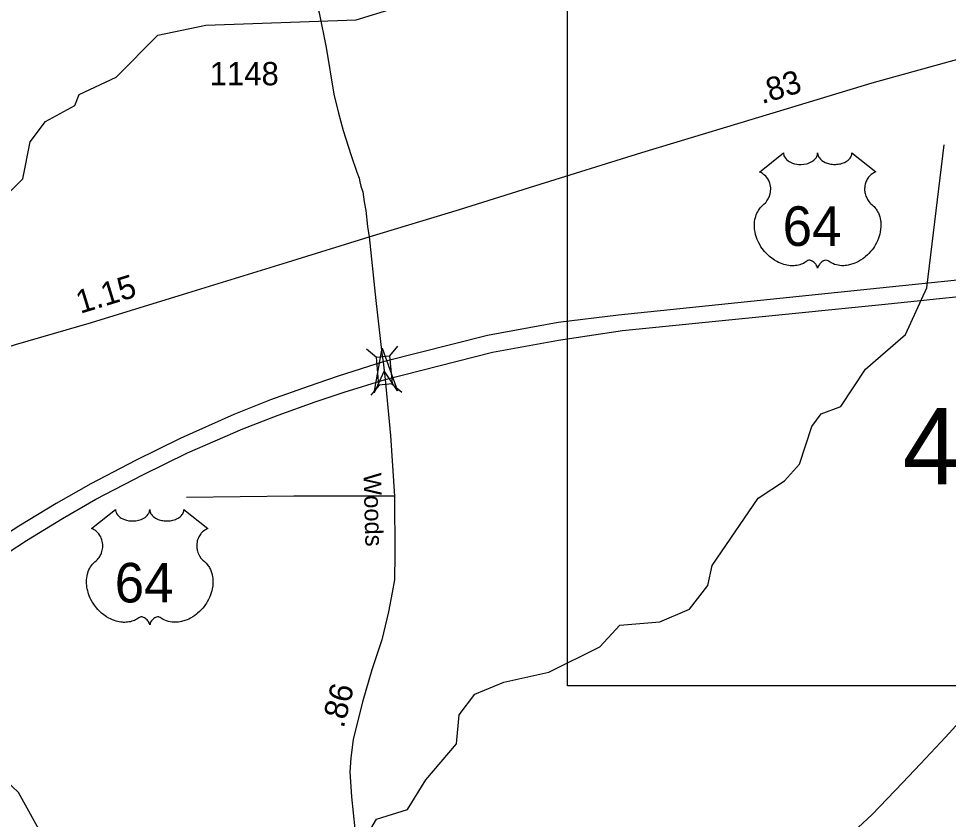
# Model space of a CAD drawing. Extents: x 2220236 to 2384410, y 720751 to 894131.
# Drawn here: x 2253834 to 2258834, y 792188 to 796491 of the extents above; entities that cross this region are included whole.
import ezdxf

# ---------------------------------------------------------------- set-up
doc = ezdxf.new("R2010")
doc.units = 0
for name, color, linetype in [('Exist Hydrographic Misc Water Feature', 7, 'Continuous'), ('Exist Hydrographic River Shore', 7, 'Continuous'), ('Exist Road Non-System Type 51', 7, 'Continuous'), ('Exist Road Primary US Attributed', 7, 'Continuous'), ('Exist Road Primary US Divided Attributed', 7, 'Continuous'), ('Exist Road Primary US Mileage Hundredths English Label', 7, 'Continuous'), ('Exist Road Primary US Shield CELL', 7, 'Continuous'), ('Exist Road Primary US Shield Number Label', 7, 'Continuous'), ('Exist Road Secondary Mileage Hundredths English Label', 7, 'Continuous'), ('Exist Road Secondary Structure Standard Bridge Attributed CELL', 7, 'Continuous'), ('Exist Road Secondary Structure Standard Bridge CELL', 7, 'Continuous'), ('Exist Road Secondary Structure Standard Bridge Number Label', 7, 'Continuous'), ('Exist Road Secondary Type 51 Attributed', 7, 'Continuous'), ('Exist Road Secondary Type 51 Label', 7, 'Continuous'), ('Exist Road Secondary Type 51 Number Label', 7, 'Continuous'), ('Map Preparation Inset Cut Line', 7, 'Continuous')]:
    doc.layers.add(name, color=color, linetype=linetype)

msp = doc.modelspace()

# ---------------------------------------------------------------- linework, layer by layer
at = {"layer": 'Exist Hydrographic Misc Water Feature'}
for points in [[(2253748.7, 795519.9), (2253856.7, 795629.2), (2253896.7, 795828.5), (2253978.8, 795938.3), (2254136.6, 796023.6), (2254160.8, 796082.2), (2254359.7, 796176.4), (2254583.7, 796401.4), (2254840.8, 796455.2), (2255648.7, 796484.4), (2255848.8, 796545.9), (2256338.7, 796607.9), (2256961.9, 796903.4), (2257160.8, 796938.6), (2257452.8, 796949.1), (2257775.7, 797103.1), (2258333.9, 797130.9), (2258574.8, 797201.4)], [(2255388.7, 791559.9), (2255758.8, 792188.6), (2255924.7, 792241), (2256023.7, 792399.6), (2256188.8, 792593), (2256203.8, 792750.2), (2256286.8, 792860), (2256443.7, 792925.6), (2256685.6, 792979.7), (2256958.8, 793115.1), (2257066.8, 793230.9), (2257282.8, 793249.4), (2257440.7, 793318.3), (2257539.7, 793444.2), (2257563.7, 793551.9), (2257810.8, 793914.2), (2257951.9, 794006.4), (2258033.7, 794096.6), (2258098.7, 794298.6), (2258148.7, 794366.5), (2258255.7, 794406.8), (2258387.8, 794607.5), (2258602.7, 794793.3), (2258717.7, 795043.5), (2258810.8, 795812.4)]]:
    msp.add_lwpolyline(points, dxfattribs=at)
at = {"layer": 'Exist Hydrographic River Shore'}
msp.add_lwpolyline([(2254150.4, 790183.6), (2254130.6, 791541.4), (2254030, 791980.1), (2253833.2, 792333.2), (2253627.6, 792526.2), (2252824.7, 793146.7), (2252625.1, 793297.2), (2252614.4, 793340.7)], dxfattribs=at)
at = {"layer": 'Exist Road Non-System Type 51'}
msp.add_lwpolyline([(2255855, 793925.2), (2255314.9, 793924.4), (2254736.7, 793917.3)], dxfattribs=at)
at = {"layer": 'Exist Road Primary US Attributed'}
for points in [[(2255718.4, 795318.5), (2256204.1, 795465.7), (2256609.7, 795592.8), (2257184.6, 795771.1), (2257968.9, 796007.5), (2258423.5, 796145.7), (2259117, 796337.6), (2259427.4, 796441.4), (2259619.1, 796527.6), (2259753, 796597.1), (2259868.1, 796674.9)], [(2252127.3, 793744.5), (2252336, 793925), (2252643.5, 794181.4), (2252786.1, 794285.1), (2252922, 794369.8), (2253057.9, 794447.8), (2253231.7, 794530.3), (2253410, 794599.4), (2253508, 794637.4), (2253817.7, 794738.8), (2254225.5, 794857), (2254744.7, 795016.4), (2255279.4, 795182.5), (2255718.4, 795318.5)]]:
    msp.add_lwpolyline(points, dxfattribs=at)
at = {"layer": 'Exist Road Primary US Divided Attributed'}
for points in [[(2261043.7, 795303.1), (2260798.9, 795273.5), (2260566.2, 795251.2), (2259859.3, 795176), (2259142.6, 795112.5), (2258465.6, 795042.5), (2257059.5, 794897.7), (2256736.2, 794858), (2256356.1, 794788), (2255794.9, 794646.3)], [(2255804.7, 794551.2), (2256382.5, 794698.1), (2256738.1, 794763.4), (2257082.2, 794814.5), (2258475, 794955.4), (2259148.3, 795023.6), (2259862.7, 795094), (2260583.2, 795165.8), (2260783.6, 795187.4), (2261013.7, 795209.7)], [(2255794.9, 794646.3), (2255552.3, 794569.4), (2255391.6, 794513.6), (2255189.2, 794441.7), (2254992.4, 794363.5), (2254702.2, 794235.2), (2254462.8, 794116.7), (2254223.4, 793990.8), (2254037.2, 793884.4), (2253836.5, 793763.4), (2253512.4, 793555.3), (2252847.4, 793100.4)], [(2252791.7, 792947.9), (2253580.1, 793492.4), (2253877.6, 793685.9), (2254071, 793804.5), (2254250, 793908.6), (2254501.5, 794039.2), (2254743.3, 794157.8), (2255040.8, 794286), (2255230.8, 794360.3), (2255428.5, 794431.3), (2255585.4, 794484.3), (2255804.7, 794551.2)]]:
    msp.add_lwpolyline(points, dxfattribs=at)
at = {"layer": 'Exist Road Primary US Shield CELL'}
for points in [[(2257946.6, 795768.8), (2257947, 795763.5), (2257948.2, 795757.2), (2257949.2, 795753.9), (2257952.2, 795747.7), (2257957.1, 795740.3), (2257963.8, 795733.1), (2257971.5, 795726.8), (2257976.7, 795723.4), (2257985.5, 795718.7), (2257995.4, 795714.5), (2258006.5, 795711.3), (2258017.8, 795709.1), (2258030.2, 795707.7), (2258042.4, 795707.5), (2258055.6, 795708.5), (2258070.2, 795711.3), (2258077, 795713), (2258084.5, 795715.6), (2258091.5, 795718.5), (2258099.2, 795722.6), (2258105.3, 795726.5), (2258110.1, 795730), (2258117, 795736.6), (2258122.4, 795743.3), (2258124.7, 795747.1), (2258126.6, 795750.8), (2258129.3, 795758.5), (2258130.1, 795762), (2258130.6, 795769.1), (2258131.1, 795763.1), (2258131.7, 795759.4), (2258132.7, 795755.7), (2258134.2, 795751.8), (2258136.9, 795746.4), (2258140, 795741.8), (2258145.7, 795735.1), (2258149.3, 795731.7), (2258152.5, 795729.1), (2258161.3, 795723), (2258171.5, 795717.9), (2258176.5, 795715.7), (2258181.7, 795713.9), (2258188.2, 795711.9), (2258195, 795710.3), (2258201.6, 795709.1), (2258208.5, 795708.2), (2258215.5, 795707.6), (2258221.2, 795707.5), (2258228.1, 795707.5), (2258234.6, 795707.9), (2258241.2, 795708.7), (2258248.5, 795709.9), (2258254.4, 795711.2), (2258262.1, 795713.2), (2258269.1, 795715.8), (2258275.2, 795718.4), (2258283.2, 795722.6), (2258289.7, 795726.6), (2258294.4, 795730.4), (2258300, 795735.6), (2258305.3, 795741.7), (2258308.4, 795746.2), (2258310.6, 795750.9), (2258312.7, 795755.7), (2258313.9, 795760.9), (2258314.5, 795765.4), (2258314.7, 795769.2), (2258443.3, 795666.8), (2258440.2, 795665.6), (2258433.2, 795662.2), (2258427.7, 795658.9), (2258418.9, 795652.7), (2258415.1, 795649.3), (2258411.3, 795645.7), (2258407.8, 795641.9), (2258404.7, 795638.3), (2258401, 795633.2), (2258397.6, 795628), (2258394.4, 795622.3), (2258392, 795617.3), (2258388, 795607), (2258386.1, 795600.5), (2258384.9, 795594.9), (2258383.4, 795583.5), (2258383, 795578), (2258383, 795572.6), (2258383.3, 795566.9), (2258383.8, 795561.4), (2258384.8, 795555.7), (2258385.7, 795550.7), (2258387.3, 795544.6), (2258389.6, 795537.4), (2258392.4, 795530.5), (2258398.3, 795519.3), (2258405.9, 795507.9), (2258411.3, 795501.5), (2258416.6, 795496.1), (2258424.5, 795489.4), (2258428.8, 795485.6), (2258433.7, 795480.6), (2258441.8, 795471.3), (2258445.1, 795466.9), (2258448.4, 795462), (2258451.4, 795456.9), (2258454.4, 795451.4), (2258456.9, 795446.6), (2258461.4, 795435.6), (2258464.7, 795424.9), (2258466.2, 795419.3), (2258468.6, 795406.6), (2258469.5, 795400.4), (2258470.5, 795388.1), (2258470.5, 795373.2), (2258469.4, 795359.1), (2258466.7, 795342.6), (2258464.5, 795332.7), (2258461.2, 795321.2), (2258457.9, 795311.3), (2258452, 795296.6), (2258446.8, 795286), (2258440, 795273.5), (2258435.4, 795266), (2258430, 795257.9), (2258423.3, 795248.7), (2258415.4, 795238.8), (2258405.9, 795228.4), (2258398.2, 795220.7), (2258388.2, 795211.7), (2258382.1, 795206.7), (2258373.4, 795200.2), (2258361.6, 795192.3), (2258349.9, 795185.5), (2258339.9, 795180.4), (2258331.1, 795176.6), (2258319.7, 795172.3), (2258300.8, 795167.1), (2258293.8, 795165.6), (2258285.6, 795164.4), (2258278, 795163.6), (2258270.5, 795163.2), (2258260.5, 795163.2), (2258250.6, 795163.9), (2258241.1, 795165.3), (2258231.3, 795167.4), (2258221.1, 795170.4), (2258211.8, 795174), (2258202.4, 795178.7), (2258186.5, 795188.7), (2258181.9, 795191.1), (2258179.3, 795191.8), (2258173.1, 795192.1), (2258167.4, 795190.9), (2258161.4, 795188.6), (2258157.9, 795186.7), (2258153.1, 795183.5), (2258149.5, 795180.7), (2258145.1, 795176.5), (2258142, 795173), (2258139.7, 795170.2), (2258135.2, 795163.2), (2258133.6, 795159.8), (2258132, 795155.5), (2258130.5, 795149.1), (2258128.5, 795157.2), (2258126.1, 795162.5), (2258123.4, 795167.1), (2258120.5, 795171.1), (2258116.1, 795176.2), (2258112, 795180.1), (2258107.2, 795184.1), (2258102, 795187.2), (2258097.9, 795189.3), (2258094.1, 795190.8), (2258089.4, 795191.9), (2258085.6, 795192.2), (2258082.5, 795192.1), (2258078.2, 795191.2), (2258072.4, 795187), (2258066.9, 795183.2), (2258060.9, 795179.4), (2258053.8, 795175.6), (2258048.5, 795173.2), (2258042.3, 795170.8), (2258035, 795168.3), (2258027.1, 795166.3), (2258019, 795164.7), (2258011.8, 795163.6), (2258004.2, 795162.9), (2257997.3, 795162.6), (2257990.1, 795162.7), (2257983.3, 795163.2), (2257975.5, 795163.9), (2257965.8, 795165.4), (2257957.7, 795167.2), (2257949.2, 795169.5), (2257940.5, 795172.2), (2257931.1, 795175.8), (2257919.4, 795180.9), (2257911.3, 795185.1), (2257898.5, 795192.4), (2257883.4, 795202.8), (2257872.1, 795212), (2257863.8, 795219.6), (2257851.5, 795232), (2257844.4, 795240.1), (2257833.1, 795254.7), (2257825.9, 795265.3), (2257821.2, 795273), (2257814.4, 795285.5), (2257810.6, 795293.3), (2257805.7, 795304.7), (2257801.9, 795315.1), (2257798.7, 795325), (2257797, 795331.3), (2257794.6, 795342.4), (2257793.1, 795350.2), (2257791.6, 795360.9), (2257790.8, 795372.2), (2257790.7, 795382.6), (2257791, 795391.3), (2257791.9, 795401.4), (2257793.7, 795412.1), (2257795.7, 795421.3), (2257797.6, 795427.9), (2257800.3, 795436), (2257803.9, 795444.9), (2257808.2, 795453.4), (2257812.2, 795460.4), (2257817.3, 795468), (2257822.3, 795474.5), (2257828.9, 795481.6), (2257835.7, 795488.2), (2257842, 795493.3), (2257849.4, 795500.6), (2257853.3, 795505), (2257858, 795511.1), (2257861.7, 795516.8), (2257864.7, 795521.9), (2257868.6, 795529.4), (2257870.9, 795535.1), (2257873.9, 795543.7), (2257875.4, 795549.8), (2257876.9, 795557.6), (2257877.9, 795565), (2257878.3, 795574.2), (2257878, 795581.8), (2257877.1, 795590.7), (2257875.4, 795599.2), (2257873.4, 795606.6), (2257870.2, 795615.1), (2257867.3, 795621.4), (2257862.3, 795629.8), (2257856.8, 795637.6), (2257851.2, 795644), (2257845.5, 795649.7), (2257840, 795654), (2257834.8, 795657.7), (2257828.3, 795661.6), (2257822, 795664.8), (2257818, 795666.4)], [(2254355.5, 793852.7), (2254355.9, 793847.4), (2254357.2, 793841.1), (2254358.1, 793837.8), (2254361.1, 793831.6), (2254366, 793824.2), (2254372.8, 793817), (2254380.4, 793810.7), (2254385.6, 793807.3), (2254394.4, 793802.6), (2254404.3, 793798.4), (2254415.4, 793795.3), (2254426.7, 793793), (2254439.1, 793791.6), (2254451.3, 793791.4), (2254464.5, 793792.4), (2254479.1, 793795.2), (2254485.9, 793796.9), (2254493.4, 793799.5), (2254500.4, 793802.4), (2254508.1, 793806.5), (2254514.2, 793810.5), (2254519, 793813.9), (2254525.9, 793820.5), (2254531.3, 793827.2), (2254533.6, 793831), (2254535.6, 793834.7), (2254538.3, 793842.4), (2254539, 793845.9), (2254539.6, 793853), (2254540, 793847), (2254540.6, 793843.3), (2254541.6, 793839.6), (2254543.1, 793835.8), (2254545.8, 793830.3), (2254548.9, 793825.7), (2254554.6, 793819), (2254558.2, 793815.6), (2254561.5, 793813), (2254570.2, 793807), (2254580.4, 793801.8), (2254585.4, 793799.6), (2254590.6, 793797.8), (2254597.1, 793795.8), (2254603.9, 793794.2), (2254610.6, 793793.1), (2254617.4, 793792.1), (2254624.4, 793791.5), (2254630.1, 793791.4), (2254637.1, 793791.5), (2254643.5, 793791.8), (2254650.1, 793792.6), (2254657.4, 793793.8), (2254663.3, 793795.1), (2254671, 793797.2), (2254678, 793799.7), (2254684.2, 793802.3), (2254692.1, 793806.5), (2254698.6, 793810.5), (2254703.3, 793814.3), (2254708.9, 793819.5), (2254714.2, 793825.7), (2254717.3, 793830.1), (2254719.5, 793834.8), (2254721.6, 793839.6), (2254722.8, 793844.8), (2254723.5, 793849.3), (2254723.6, 793853.1), (2254852.2, 793750.7), (2254849.1, 793749.5), (2254842.2, 793746.1), (2254836.6, 793742.8), (2254827.8, 793736.6), (2254824, 793733.2), (2254820.2, 793729.6), (2254816.7, 793725.8), (2254813.6, 793722.2), (2254809.9, 793717.1), (2254806.5, 793711.9), (2254803.3, 793706.2), (2254800.9, 793701.3), (2254796.9, 793690.9), (2254795, 793684.4), (2254793.8, 793678.8), (2254792.3, 793667.4), (2254791.9, 793661.9), (2254791.9, 793656.5), (2254792.2, 793650.8), (2254792.8, 793645.3), (2254793.7, 793639.6), (2254794.7, 793634.6), (2254796.2, 793628.5), (2254798.5, 793621.3), (2254801.3, 793614.4), (2254807.2, 793603.2), (2254814.8, 793591.8), (2254820.2, 793585.5), (2254825.5, 793580), (2254833.4, 793573.3), (2254837.7, 793569.5), (2254842.7, 793564.6), (2254850.7, 793555.2), (2254854, 793550.8), (2254857.3, 793545.9), (2254860.3, 793540.8), (2254863.3, 793535.3), (2254865.8, 793530.5), (2254870.3, 793519.5), (2254873.6, 793508.8), (2254875.1, 793503.2), (2254877.5, 793490.5), (2254878.4, 793484.3), (2254879.4, 793472), (2254879.4, 793457.1), (2254878.3, 793443), (2254875.6, 793426.5), (2254873.4, 793416.6), (2254870.1, 793405.1), (2254866.8, 793395.2), (2254860.9, 793380.5), (2254855.7, 793369.9), (2254849, 793357.4), (2254844.3, 793349.9), (2254838.9, 793341.8), (2254832.2, 793332.6), (2254824.3, 793322.7), (2254814.8, 793312.3), (2254807.1, 793304.6), (2254797.1, 793295.6), (2254791, 793290.6), (2254782.3, 793284.1), (2254770.5, 793276.2), (2254758.8, 793269.4), (2254748.9, 793264.3), (2254740, 793260.5), (2254728.7, 793256.2), (2254709.7, 793251), (2254702.8, 793249.5), (2254694.6, 793248.3), (2254686.9, 793247.5), (2254679.4, 793247.1), (2254669.4, 793247.1), (2254659.5, 793247.8), (2254650.1, 793249.2), (2254640.3, 793251.3), (2254630, 793254.3), (2254620.7, 793258), (2254611.3, 793262.6), (2254595.4, 793272.6), (2254590.8, 793275), (2254588.2, 793275.7), (2254582, 793276), (2254576.3, 793274.8), (2254570.3, 793272.5), (2254566.8, 793270.6), (2254562, 793267.4), (2254558.4, 793264.6), (2254554, 793260.4), (2254550.9, 793256.9), (2254548.6, 793254.1), (2254544.1, 793247.1), (2254542.5, 793243.7), (2254540.9, 793239.4), (2254539.4, 793233), (2254537.4, 793241.1), (2254535, 793246.4), (2254532.3, 793251), (2254529.4, 793255), (2254525, 793260.2), (2254520.9, 793264), (2254516.1, 793268), (2254510.9, 793271.1), (2254506.8, 793273.2), (2254503, 793274.7), (2254498.3, 793275.8), (2254494.5, 793276.1), (2254491.4, 793276), (2254487.2, 793275.1), (2254481.3, 793270.9), (2254475.8, 793267.1), (2254469.8, 793263.3), (2254462.7, 793259.5), (2254457.4, 793257.1), (2254451.2, 793254.7), (2254443.9, 793252.2), (2254436, 793250.2), (2254427.9, 793248.6), (2254420.8, 793247.5), (2254413.1, 793246.8), (2254406.2, 793246.6), (2254399, 793246.6), (2254392.2, 793247.2), (2254384.4, 793247.8), (2254374.7, 793249.3), (2254366.6, 793251.1), (2254358.1, 793253.4), (2254349.4, 793256.1), (2254340, 793259.7), (2254328.3, 793264.8), (2254320.2, 793269), (2254307.4, 793276.3), (2254292.3, 793286.7), (2254281, 793295.9), (2254272.7, 793303.5), (2254260.4, 793315.9), (2254253.3, 793324.1), (2254242, 793338.6), (2254234.8, 793349.2), (2254230.1, 793357), (2254223.3, 793369.4), (2254219.5, 793377.2), (2254214.6, 793388.6), (2254210.8, 793399.1), (2254207.6, 793408.9), (2254205.9, 793415.2), (2254203.5, 793426.3), (2254202, 793434.1), (2254200.6, 793444.8), (2254199.8, 793456.1), (2254199.6, 793466.5), (2254199.9, 793475.2), (2254200.9, 793485.3), (2254202.6, 793496), (2254204.6, 793505.2), (2254206.5, 793511.8), (2254209.2, 793519.9), (2254212.8, 793528.8), (2254217.1, 793537.3), (2254221.1, 793544.3), (2254226.2, 793551.9), (2254231.2, 793558.4), (2254237.8, 793565.5), (2254244.6, 793572.1), (2254250.9, 793577.2), (2254258.4, 793584.5), (2254262.2, 793588.9), (2254266.9, 793595), (2254270.6, 793600.7), (2254273.6, 793605.8), (2254277.5, 793613.3), (2254279.9, 793619), (2254282.8, 793627.6), (2254284.3, 793633.7), (2254285.8, 793641.5), (2254286.8, 793648.9), (2254287.2, 793658.1), (2254287, 793665.7), (2254286, 793674.6), (2254284.3, 793683.1), (2254282.3, 793690.5), (2254279.1, 793699.1), (2254276.2, 793705.3), (2254271.2, 793713.7), (2254265.8, 793721.5), (2254260.1, 793727.9), (2254254.4, 793733.6), (2254248.9, 793737.9), (2254243.7, 793741.6), (2254237.2, 793745.6), (2254230.9, 793748.7), (2254226.9, 793750.3)]]:
    msp.add_lwpolyline(points, close=True, dxfattribs=at)
at = {"layer": 'Exist Road Secondary Structure Standard Bridge Attributed CELL'}
msp.add_lwpolyline([(2255746.5, 794479.9), (2255788.7, 794720), (2255872.3, 794491), (2255799.4, 794598.6)], close=True, dxfattribs=at)
at = {"layer": 'Exist Road Secondary Structure Standard Bridge CELL'}
for p, q in [((2255872.4, 794731.1), (2255828.3, 794678)), ((2255705, 794715.6), (2255758, 794671.5)), ((2255773.2, 794521.1), (2255729.1, 794468.1)), ((2255841.9, 794527.5), (2255895, 794483.4))]:
    msp.add_line(p, q, dxfattribs=at)
msp.add_lwpolyline([(2255828.3, 794678), (2255842.2, 794527.5), (2255771.9, 794521), (2255758, 794671.5)], close=True, dxfattribs=at)
at = {"layer": 'Exist Road Secondary Type 51 Attributed'}
for points in [[(2255162.9, 797760.7), (2255241.4, 797419.9), (2255281.7, 797214.8), (2255335.3, 797001.8), (2255373, 796811.3), (2255413.1, 796666.3), (2255451, 796521.4), (2255488.9, 796336.3), (2255529, 796084.4), (2255553.5, 795982.9), (2255580.2, 795889.3), (2255622.6, 795755.5), (2255653.8, 795666.3), (2255664.9, 795632.9), (2255668.6, 795614.3), (2255674.6, 795590.5), (2255685, 795559.3), (2255691.7, 795506.9), (2255701.7, 795460), (2255709.5, 795374.3), (2255718.4, 795318.5)], [(2255718.4, 795318.5), (2255755.8, 794975.4), (2255788.2, 794693.2), (2255794.9, 794646.3)], [(2255794.9, 794646.3), (2255804.7, 794551.2)], [(2255804.7, 794551.2), (2255834.3, 794250.5), (2255855, 793925.2), (2255857.7, 793613.6), (2255854.9, 793475.5), (2255843.2, 793407.7), (2255822.4, 793303.5), (2255787.5, 793153.5), (2255733.1, 792990.9), (2255684.5, 792824.6), (2255632.4, 792618.4), (2255620.4, 792517), (2255615.9, 792443.4), (2255624.8, 792309.6), (2255651.6, 792051)], [(2257420.7, 791675.5), (2257632.4, 791727.7), (2257761.7, 791772.3), (2257839.7, 791805.7), (2257951.1, 791854.8), (2258060.3, 791923.9), (2258149.4, 791984.1), (2258231.8, 792044.3), (2258323.2, 792120.1), (2258423.5, 792213.7), (2258586.1, 792384.3), (2258684.2, 792486.9), (2258817.9, 792629.6), (2259045.1, 792878.2), (2259138.7, 792974), (2260012.1, 793924.8), (2260168.4, 794094.3)]]:
    msp.add_lwpolyline(points, dxfattribs=at)
at = {"layer": 'Map Preparation Inset Cut Line'}
msp.add_line((2256785.4, 794750.3), (2256785.4, 794792), dxfattribs=at)
msp.add_line((2256785.4, 794750.3), (2256785.4, 794792), dxfattribs=at)
msp.add_lwpolyline([(2256785.4, 804809.4), (2269207.8, 804809.4), (2269207.8, 792904.9), (2256785.4, 792904.9), (2256785.4, 804809.4)], dxfattribs=at)
msp.add_lwpolyline([(2256785.4, 804809.4), (2269207.8, 804809.4), (2269207.8, 792904.9), (2256785.4, 792904.9), (2256785.4, 804809.4)], dxfattribs=at)

# ---------------------------------------------------------------- texts
at = {"layer": 'Exist Road Primary US Mileage Hundredths English Label'}
for s, rotation, p in [('.83', 16.9152, (2257831.1, 796030.9)), ('1.15', 17.0697, (2254165.8, 794904))]:
    msp.add_text(s, height=125, rotation=rotation, dxfattribs=at).set_placement(p)
at = {"layer": 'Exist Road Primary US Shield Number Label'}
for p in [(2257942.4, 795269.5), (2254351.3, 793353.4)]:
    msp.add_text('64', height=212.5, dxfattribs=at).set_placement(p)
at = {"layer": 'Exist Road Secondary Mileage Hundredths English Label'}
msp.add_text('.86', height=125, rotation=75.8201, dxfattribs=at).set_placement((2255581.9, 792673.8))
at = {"layer": 'Exist Road Secondary Structure Standard Bridge Number Label'}
msp.add_text('46', height=410.1, dxfattribs=at).set_placement((2258587.4, 793987.8))
at = {"layer": 'Exist Road Secondary Type 51 Label'}
msp.add_text('Woods', height=95, rotation=271.5668, dxfattribs=at).set_placement((2255688.8, 794048.4))
at = {"layer": 'Exist Road Secondary Type 51 Number Label'}
msp.add_text('1148', height=125, dxfattribs=at).set_placement((2254861.8, 796132.5))

doc.saveas('drawing.dxf')
